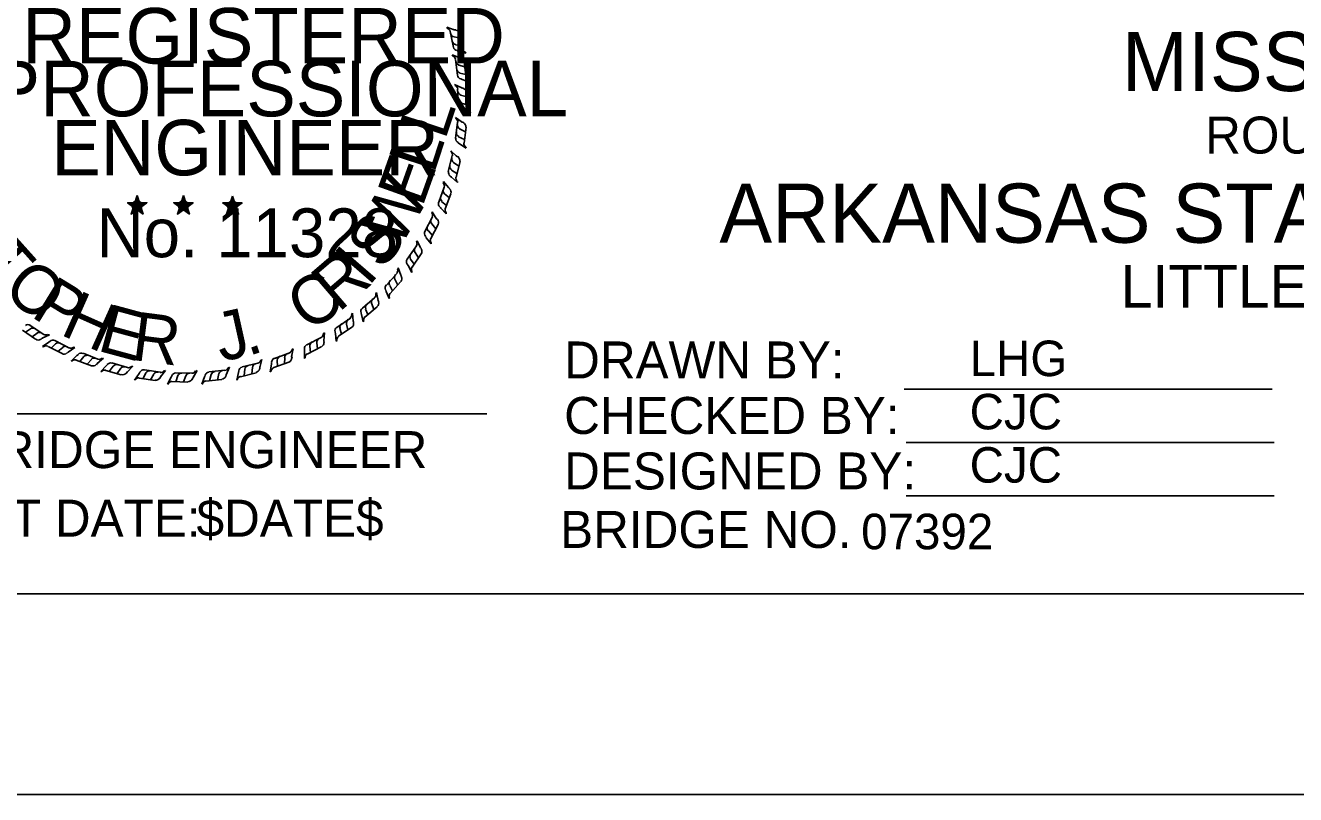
# Model space of a CAD drawing. Extents: x -193 to 149, y 507 to 725.
# Drawn here: x 58.22 to 101.13, y 507.07 to 533.07 of the extents above; entities that cross this region are included whole.
import ezdxf

# ---------------------------------------------------------------- set-up
doc = ezdxf.new("R2010")
doc.units = 0
for name, color, linetype in [('border', 7, 'Continuous'), ('Border 2660-Hwy18 - Level 62', 7, 'Continuous'), ('Border 2660-Hwy18 - Stamp-ChrisC', 7, 'Continuous'), ('Border 2660-Hwy18 - Text', 7, 'Continuous'), ('Border 2660-Hwy18 - Title Text', 7, 'Continuous'), ('Bridge No BLFR', 7, 'Continuous'), ('Text', 7, 'Continuous')]:
    doc.layers.add(name, color=color, linetype=linetype)

msp = doc.modelspace()

# ---------------------------------------------------------------- linework, layer by layer
at = {"layer": 'border'}
for p, q in [((87.907, 520.772), (100.339, 520.772)), ((52.387, 519.944), (73.807, 519.944)), ((87.979, 518.972), (100.411, 518.972)), ((87.979, 517.172), (100.411, 517.172)), ((143.779, 513.86), (-176.332, 513.86))]:
    msp.add_line(p, q, dxfattribs=at)
at = {"layer": 'Border 2660-Hwy18 - Level 62'}
msp.add_lwpolyline([(-192.533, 725.169), (148.651, 725.169), (148.651, 507.073), (-192.533, 507.073)], close=True, dxfattribs=at)
at = {"layer": 'Border 2660-Hwy18 - Stamp-ChrisC'}
for p, q in [((72.712, 532.92), (72.457, 533.01)), ((72.457, 533.01), (72.48, 532.965)), ((72.682, 532.328), (72.577, 532.868)), ((72.712, 532.92), (72.69, 532.928)), ((72.705, 532.68), (72.915, 532.643)), ((72.765, 532.92), (72.712, 532.92)), ((72.885, 532.785), (72.99, 532.26)), ((72.757, 532.41), (72.967, 532.388)), ((72.81, 532.215), (72.855, 532.2)), ((72.855, 532.2), (73.11, 532.133)), ((73.11, 532.133), (73.095, 532.155)), ((72.9, 531.975), (72.645, 532.073)), ((72.645, 532.073), (72.667, 532.035)), ((72.817, 531.383), (72.75, 531.923)), ((72.9, 531.975), (72.87, 531.975)), ((72.87, 531.728), (73.072, 531.675)), ((72.952, 531.968), (72.9, 531.975)), ((73.05, 531.825), (73.117, 531.285)), ((72.9, 531.458), (73.102, 531.413)), ((72.937, 531.263), (72.982, 531.24)), ((72.982, 531.24), (73.23, 531.15)), ((72.967, 530.955), (72.72, 531.075)), ((72.72, 531.075), (72.757, 531.038)), ((72.855, 530.37), (72.825, 530.918)), ((72.967, 530.955), (72.945, 530.963)), ((73.035, 530.94), (72.967, 530.955)), ((73.23, 531.15), (73.222, 531.18)), ((72.922, 530.708), (73.147, 530.655)), ((72.945, 530.445), (73.155, 530.385)), ((73.132, 530.798), (73.17, 530.258)), ((72.975, 529.8), (72.75, 529.958)), ((72.75, 529.958), (72.78, 529.913)), ((72.967, 530.243), (73.012, 530.22)), ((73.012, 530.22), (73.26, 530.115)), ((73.26, 530.115), (73.245, 530.145)), ((72.757, 529.253), (72.825, 529.8)), ((72.885, 529.575), (73.087, 529.47)), ((72.975, 529.8), (72.952, 529.815)), ((73.035, 529.785), (72.975, 529.8)), ((73.11, 529.628), (73.042, 529.095)), ((72.847, 529.103), (72.885, 529.073)), ((72.855, 529.305), (73.057, 529.215)), ((72.51, 528.128), (72.645, 528.668)), ((72.795, 528.645), (72.592, 528.833)), ((72.592, 528.833), (72.615, 528.788)), ((72.795, 528.645), (72.78, 528.668)), ((72.885, 529.073), (73.11, 528.923)), ((73.11, 528.923), (73.102, 528.96)), ((72.682, 528.435), (72.862, 528.308)), ((72.907, 528.465), (72.772, 527.94)), ((72.855, 528.623), (72.795, 528.645)), ((72.577, 527.978), (72.622, 527.94)), ((72.615, 528.173), (72.802, 528.06)), ((72.622, 527.94), (72.817, 527.76)), ((72.187, 527.093), (72.375, 527.603)), ((72.352, 527.79), (72.345, 527.745)), ((72.517, 527.588), (72.352, 527.79)), ((72.382, 527.378), (72.547, 527.243)), ((72.592, 527.378), (72.405, 526.875)), ((72.517, 527.588), (72.502, 527.595)), ((72.562, 527.55), (72.517, 527.588)), ((72.817, 527.76), (72.817, 527.798)), ((61.672, 527.078), (61.995, 526.973)), ((61.672, 527.078), (61.912, 527.055)), ((61.672, 527.078), (61.912, 527.033)), ((61.672, 527.078), (61.897, 527.018)), ((61.672, 527.078), (61.897, 526.988)), ((61.672, 527.078), (61.89, 526.965)), ((61.672, 527.078), (61.89, 526.943)), ((61.792, 526.695), (61.995, 526.973)), ((61.792, 526.695), (61.897, 526.958)), ((61.995, 527.318), (61.942, 527.085)), ((61.995, 527.318), (61.957, 527.078)), ((61.995, 527.318), (61.98, 527.078)), ((61.995, 526.973), (61.995, 527.318)), ((61.995, 527.318), (62.062, 527.078)), ((61.995, 527.318), (62.047, 527.078)), ((61.995, 527.318), (62.017, 527.085)), ((62.325, 527.078), (61.995, 526.973)), ((62.197, 526.695), (61.995, 526.973)), ((62.325, 527.078), (62.032, 527.055)), ((62.325, 527.078), (62.055, 527.033)), ((62.325, 527.078), (62.055, 527.01)), ((62.197, 526.695), (62.07, 526.965)), ((62.197, 526.695), (62.092, 526.973)), ((62.325, 527.078), (62.115, 526.995)), ((62.325, 527.078), (62.13, 526.98)), ((62.325, 527.078), (62.145, 526.973)), ((63.232, 527.078), (63.562, 526.973)), ((63.232, 527.078), (63.472, 527.055)), ((63.232, 527.078), (63.472, 527.033)), ((63.232, 527.078), (63.465, 527.018)), ((63.232, 527.078), (63.457, 526.988)), ((63.232, 527.078), (63.457, 526.965)), ((63.232, 527.078), (63.457, 526.943)), ((63.36, 526.695), (63.562, 526.973)), ((63.36, 526.695), (63.465, 526.958)), ((63.562, 527.318), (63.51, 527.085)), ((63.562, 527.318), (63.525, 527.078)), ((63.562, 527.318), (63.547, 527.078)), ((63.562, 526.973), (63.562, 527.318)), ((63.562, 527.318), (63.622, 527.078)), ((63.562, 527.318), (63.607, 527.078)), ((63.562, 527.318), (63.585, 527.085)), ((63.885, 527.078), (63.562, 526.973)), ((63.765, 526.695), (63.562, 526.973)), ((63.885, 527.078), (63.6, 527.055)), ((63.885, 527.078), (63.622, 527.033)), ((63.885, 527.078), (63.622, 527.01)), ((63.765, 526.695), (63.637, 526.965)), ((63.765, 526.695), (63.652, 526.973)), ((63.885, 527.078), (63.682, 526.995)), ((63.885, 527.078), (63.697, 526.98)), ((63.885, 527.078), (63.712, 526.973)), ((64.89, 527.07), (65.22, 526.965)), ((64.89, 527.07), (65.13, 527.04)), ((64.89, 527.07), (65.13, 527.025)), ((64.89, 527.07), (65.122, 527.01)), ((64.89, 527.07), (65.122, 526.973)), ((64.89, 527.07), (65.115, 526.95)), ((64.89, 527.07), (65.115, 526.935)), ((65.017, 526.688), (65.22, 526.965)), ((65.22, 527.303), (65.167, 527.078)), ((65.22, 527.303), (65.182, 527.07)), ((65.22, 527.303), (65.205, 527.07)), ((65.22, 526.965), (65.22, 527.303)), ((65.22, 527.303), (65.28, 527.07)), ((65.22, 527.303), (65.265, 527.07)), ((65.22, 527.303), (65.242, 527.07)), ((65.542, 527.07), (65.22, 526.965)), ((65.422, 526.688), (65.22, 526.965)), ((65.542, 527.07), (65.257, 527.048)), ((65.542, 527.07), (65.28, 527.018)), ((65.542, 527.07), (65.28, 527.003)), ((65.422, 526.688), (65.287, 526.958)), ((65.422, 526.688), (65.31, 526.958)), ((65.542, 527.07), (65.332, 526.98)), ((65.542, 527.07), (65.355, 526.973)), ((65.542, 527.07), (65.37, 526.958)), ((72.285, 527.123), (72.45, 526.988)), ((61.792, 526.695), (61.912, 526.928)), ((61.792, 526.695), (61.927, 526.913)), ((61.792, 526.695), (61.995, 526.898)), ((61.792, 526.695), (61.957, 526.89)), ((61.792, 526.695), (62.002, 526.875)), ((62.197, 526.695), (61.995, 526.898)), ((62.197, 526.695), (61.995, 526.868)), ((62.197, 526.695), (62.032, 526.89)), ((62.197, 526.695), (62.062, 526.928)), ((63.36, 526.695), (63.48, 526.928)), ((63.36, 526.695), (63.495, 526.913)), ((63.36, 526.695), (63.562, 526.898)), ((63.36, 526.695), (63.525, 526.89)), ((63.36, 526.695), (63.57, 526.875)), ((63.765, 526.695), (63.562, 526.898)), ((63.765, 526.695), (63.562, 526.868)), ((63.765, 526.695), (63.592, 526.89)), ((63.765, 526.695), (63.622, 526.928)), ((65.017, 526.688), (65.122, 526.943)), ((65.017, 526.688), (65.137, 526.913)), ((65.017, 526.688), (65.152, 526.905)), ((65.017, 526.688), (65.182, 526.883)), ((65.017, 526.688), (65.212, 526.883)), ((65.017, 526.688), (65.227, 526.86)), ((65.422, 526.688), (65.212, 526.883)), ((65.422, 526.688), (65.212, 526.86)), ((65.422, 526.688), (65.257, 526.883)), ((65.422, 526.688), (65.287, 526.913)), ((71.722, 526.103), (71.977, 526.598)), ((71.962, 526.77), (71.955, 526.725)), ((72.105, 526.545), (71.962, 526.77)), ((72.105, 526.545), (72.097, 526.568)), ((72.15, 526.508), (72.105, 526.545)), ((72.232, 526.928), (72.262, 526.89)), ((72.262, 526.89), (72.442, 526.703)), ((72.442, 526.703), (72.442, 526.733)), ((71.835, 526.125), (71.97, 525.975)), ((72.165, 526.343), (71.917, 525.863)), ((71.955, 526.365), (72.09, 526.2)), ((71.452, 525.788), (71.437, 525.743)), ((71.565, 525.555), (71.452, 525.788)), ((71.745, 525.938), (71.767, 525.893)), ((71.767, 525.893), (71.925, 525.683)), ((71.925, 525.683), (71.932, 525.72)), ((71.122, 525.165), (71.437, 525.615)), ((71.595, 525.345), (71.287, 524.903)), ((71.392, 525.39), (71.505, 525.21)), ((71.565, 525.555), (71.55, 525.578)), ((71.602, 525.518), (71.565, 525.555)), ((70.815, 524.88), (70.8, 524.835)), ((70.905, 524.625), (70.815, 524.88)), ((71.122, 525), (71.152, 524.955)), ((71.152, 524.955), (71.272, 524.715)), ((71.235, 525.165), (71.355, 525)), ((70.417, 524.288), (70.777, 524.7)), ((70.897, 524.408), (70.545, 524.01)), ((70.702, 524.49), (70.8, 524.295)), ((70.905, 524.625), (70.89, 524.648)), ((70.927, 524.58), (70.905, 524.625)), ((71.272, 524.715), (71.28, 524.753)), ((70.087, 524.04), (70.065, 524.003)), ((70.14, 523.778), (70.087, 524.04)), ((70.395, 524.123), (70.41, 524.078)), ((70.41, 524.078), (70.507, 523.838)), ((70.53, 524.28), (70.627, 524.1)), ((69.607, 523.515), (70.02, 523.868)), ((70.102, 523.56), (69.69, 523.215)), ((69.922, 523.665), (69.99, 523.463)), ((70.14, 523.778), (70.132, 523.8)), ((70.162, 523.725), (70.14, 523.778)), ((70.507, 523.838), (70.522, 523.86)), ((68.745, 522.863), (69.202, 523.178)), ((69.277, 523.343), (69.24, 523.305)), ((69.3, 523.073), (69.277, 523.343)), ((69.3, 523.073), (69.3, 523.103)), ((69.562, 523.35), (69.577, 523.305)), ((69.577, 523.305), (69.637, 523.05)), ((69.712, 523.485), (69.787, 523.298)), ((58.567, 522.465), (58.125, 522.765)), ((58.395, 522.81), (58.23, 522.698)), ((58.387, 522.923), (58.845, 522.623)), ((58.62, 522.668), (58.455, 522.548)), ((68.325, 522.675), (68.287, 522.645)), ((68.31, 522.413), (68.325, 522.675)), ((68.692, 522.705), (68.7, 522.653)), ((69.255, 522.87), (68.805, 522.563)), ((68.85, 522.833), (68.902, 522.63)), ((69.075, 522.975), (69.112, 522.78)), ((69.315, 523.028), (69.3, 523.073)), ((69.637, 523.05), (69.652, 523.073)), ((58.747, 522.458), (58.785, 522.495)), ((58.785, 522.495), (59.032, 522.608)), ((58.785, 522.495), (58.807, 522.503)), ((59.017, 522.368), (58.8, 522.218)), ((59.032, 522.608), (58.987, 522.615)), ((59.055, 522.398), (59.017, 522.368)), ((59.242, 522.308), (59.092, 522.165)), ((59.22, 522.42), (59.715, 522.165)), ((67.732, 522.278), (68.212, 522.525)), ((68.07, 522.345), (68.092, 522.135)), ((68.31, 522.413), (68.302, 522.435)), ((68.317, 522.353), (68.31, 522.413)), ((68.7, 522.653), (68.722, 522.398)), ((68.722, 522.398), (68.752, 522.42)), ((58.8, 522.218), (58.837, 522.203)), ((59.467, 521.978), (58.987, 522.218)), ((59.482, 522.188), (59.317, 522.053)), ((59.632, 521.993), (59.662, 522.03)), ((59.662, 522.03), (59.895, 522.18)), ((59.662, 522.03), (59.692, 522.045)), ((59.962, 521.91), (59.767, 521.723)), ((59.895, 522.18), (59.842, 522.188)), ((60, 521.94), (59.962, 521.91)), ((60.195, 521.88), (60.06, 521.715)), ((60.172, 521.993), (60.675, 521.79)), ((60.652, 521.64), (60.862, 521.82)), ((60.862, 521.82), (60.81, 521.805)), ((66.637, 521.813), (67.155, 522.008)), ((66.982, 521.843), (66.975, 521.633)), ((67.215, 521.88), (67.267, 522.143)), ((67.215, 521.88), (67.222, 521.91)), ((67.23, 521.828), (67.215, 521.88)), ((67.267, 522.143), (67.23, 522.113)), ((67.65, 522.128), (67.65, 522.075)), ((67.65, 522.075), (67.65, 521.813)), ((67.65, 521.813), (67.672, 521.835)), ((68.22, 522.21), (67.747, 521.963)), ((67.83, 522.225), (67.852, 522.015)), ((59.767, 521.723), (59.805, 521.73)), ((60.45, 521.565), (59.94, 521.76)), ((60.45, 521.783), (60.307, 521.618)), ((60.622, 521.595), (60.652, 521.64)), ((60.652, 521.64), (60.667, 521.655)), ((60.952, 521.565), (60.772, 521.37)), ((60.772, 521.37), (60.802, 521.378)), ((61.462, 521.265), (60.937, 521.408)), ((60.99, 521.603), (60.952, 521.565)), ((61.185, 521.558), (61.057, 521.37)), ((61.147, 521.663), (61.672, 521.505)), ((61.447, 521.483), (61.32, 521.303)), ((61.657, 521.355), (61.852, 521.55)), ((61.657, 521.355), (61.672, 521.37)), ((61.852, 521.55), (61.8, 521.535)), ((62.242, 521.43), (62.782, 521.348)), ((62.79, 521.198), (62.955, 521.408)), ((62.955, 521.408), (62.91, 521.385)), ((63.885, 521.168), (64.02, 521.408)), ((64.02, 521.408), (63.975, 521.378)), ((64.425, 521.363), (64.965, 521.415)), ((65.01, 521.265), (65.122, 521.52)), ((65.122, 521.52), (65.077, 521.483)), ((65.437, 521.393), (65.422, 521.34)), ((65.542, 521.528), (66.075, 521.655)), ((65.632, 521.453), (65.617, 521.235)), ((65.895, 521.513), (65.872, 521.295)), ((66.142, 521.513), (66.21, 521.783)), ((66.142, 521.513), (66.142, 521.543)), ((66.142, 521.453), (66.142, 521.513)), ((66.21, 521.783), (66.18, 521.738)), ((66.54, 521.625), (66.495, 521.363)), ((66.495, 521.363), (66.525, 521.385)), ((66.54, 521.678), (66.54, 521.625)), ((67.125, 521.693), (66.615, 521.505)), ((66.727, 521.753), (66.735, 521.543)), ((61.627, 521.303), (61.657, 521.355)), ((62.062, 521.31), (61.905, 521.085)), ((61.905, 521.085), (61.935, 521.1)), ((62.092, 521.348), (62.062, 521.31)), ((62.602, 521.07), (62.07, 521.153)), ((62.295, 521.333), (62.197, 521.138)), ((62.557, 521.288), (62.452, 521.093)), ((62.76, 521.138), (62.79, 521.198)), ((62.79, 521.198), (62.797, 521.213)), ((63.15, 521.183), (63.022, 520.943)), ((63.022, 520.943), (63.052, 520.958)), ((63.172, 521.228), (63.15, 521.183)), ((63.712, 521.018), (63.172, 521.033)), ((63.3, 521.325), (63.847, 521.318)), ((63.375, 521.235), (63.3, 521.025)), ((63.645, 521.228), (63.562, 521.025)), ((63.862, 521.108), (63.885, 521.168)), ((63.885, 521.168), (63.892, 521.19)), ((64.275, 521.198), (64.185, 520.943)), ((64.185, 520.943), (64.215, 520.965)), ((64.297, 521.243), (64.275, 521.198)), ((64.86, 521.1), (64.32, 521.048)), ((64.5, 521.273), (64.447, 521.063)), ((64.762, 521.303), (64.71, 521.085)), ((64.995, 521.205), (65.01, 521.265)), ((65.01, 521.265), (65.017, 521.288)), ((65.422, 521.34), (65.362, 521.078)), ((65.362, 521.078), (65.392, 521.108)), ((66.015, 521.333), (65.49, 521.198))]:
    msp.add_line(p, q, dxfattribs=at)
for points in [[(61.995, 527.318), (62.197, 526.695), (61.672, 527.078), (62.325, 527.078), (61.792, 526.695), (61.995, 527.318)], [(63.562, 527.318), (63.765, 526.695), (63.232, 527.078), (63.885, 527.078), (63.36, 526.695), (63.562, 527.318)], [(65.22, 527.303), (65.422, 526.688), (64.89, 527.07), (65.542, 527.07), (65.017, 526.688), (65.22, 527.303)]]:
    msp.add_lwpolyline(points, dxfattribs=at)
for centre, radius in [((61.994, 526.977), 0.161), ((61.994, 526.977), 0.146), ((61.994, 526.977), 0.136), ((61.994, 526.977), 0.124), ((61.994, 526.977), 0.109), ((61.994, 526.977), 0.101), ((61.994, 526.977), 0.0929), ((61.994, 526.977), 0.08), ((61.994, 526.977), 0.0701), ((61.994, 526.977), 0.0583), ((61.994, 526.977), 0.0464), ((61.994, 526.977), 0.0346), ((61.994, 526.977), 0.0278), ((61.994, 526.977), 0.0135), ((63.559, 526.977), 0.161), ((63.559, 526.977), 0.146), ((63.559, 526.977), 0.136), ((63.559, 526.977), 0.124), ((63.559, 526.977), 0.109), ((63.559, 526.977), 0.101), ((63.559, 526.977), 0.0929), ((63.559, 526.977), 0.08), ((63.559, 526.977), 0.0701), ((63.559, 526.977), 0.0583), ((63.559, 526.977), 0.0464), ((63.559, 526.977), 0.0346), ((63.559, 526.977), 0.0278), ((63.559, 526.977), 0.0135), ((65.216, 526.966), 0.161), ((65.216, 526.966), 0.146), ((65.216, 526.966), 0.136), ((65.216, 526.966), 0.124), ((65.216, 526.966), 0.109), ((65.216, 526.966), 0.101), ((65.216, 526.966), 0.0929), ((65.216, 526.966), 0.08), ((65.216, 526.966), 0.0701), ((65.216, 526.966), 0.0583), ((65.216, 526.966), 0.0464), ((65.216, 526.966), 0.0346), ((65.216, 526.966), 0.0278), ((65.216, 526.966), 0.0135)]:
    msp.add_circle(centre, radius, dxfattribs=at)
for centre, start, end in [((72.435, 532.829), 15.7912, 74.579), ((72.735, 532.826), 191.5304, 259.9044), ((72.787, 532.566), 191.5304, 259.9044), ((72.738, 532.768), 11.5304, 79.9044), ((72.828, 532.365), 191.5304, 259.9044), ((73.131, 532.305), 195.7912, 254.579), ((72.609, 531.898), 11.4348, 70.2227), ((72.908, 531.872), 187.174, 255.548), ((72.907, 531.814), 7.174, 75.548), ((72.94, 531.609), 187.174, 255.548), ((72.967, 531.406), 187.174, 255.548), ((73.264, 531.322), 191.4348, 250.2227), ((72.684, 530.9), 8.033, 66.8208), ((72.981, 530.857), 183.7722, 252.1462), ((72.976, 530.799), 3.7722, 72.1462), ((72.997, 530.593), 183.7722, 252.1462), ((73.011, 530.388), 183.7722, 252.1462), ((73.303, 530.287), 188.033, 246.8208), ((72.682, 529.802), 357.57, 56.3579), ((72.966, 529.705), 173.3093, 241.6832), ((72.951, 529.649), 353.3093, 61.6832), ((72.911, 529.238), 173.3093, 241.6832), ((72.934, 529.442), 173.3093, 241.6832), ((72.504, 528.687), 350.445, 49.2329), ((73.18, 529.086), 177.57, 236.3579), ((72.71, 528.3), 166.1842, 234.5582), ((72.774, 528.556), 166.1842, 234.5582), ((72.752, 528.503), 346.1842, 54.5582), ((72.662, 528.1), 166.1842, 234.5582), ((72.91, 527.916), 170.445, 229.2329), ((72.484, 527.487), 159.9003, 228.2743), ((72.23, 527.647), 344.1611, 42.9489), ((72.457, 527.436), 339.9003, 48.2743), ((72.322, 527.046), 159.9003, 228.2743), ((72.392, 527.239), 159.9003, 228.2743), ((72.065, 526.46), 152.8541, 221.2281), ((71.833, 526.65), 337.1149, 35.9028), ((72.549, 526.836), 164.1611, 222.9489), ((71.85, 526.042), 152.8541, 221.2281), ((71.944, 526.225), 152.8541, 221.2281), ((72.031, 526.413), 332.8541, 41.2281), ((71.304, 525.691), 329.7262, 28.514), ((72.049, 525.806), 157.1149, 215.9028), ((71.359, 525.255), 145.4654, 213.8394), ((71.51, 525.472), 145.4654, 213.8394), ((71.471, 525.43), 325.4654, 33.8394), ((70.656, 524.793), 322.7822, 21.57), ((71.244, 525.086), 145.4654, 213.8394), ((71.41, 524.825), 149.7262, 208.514), ((70.659, 524.354), 138.5214, 206.8953), ((70.834, 524.551), 138.5214, 206.8953), ((70.79, 524.514), 318.5214, 26.8953), ((69.917, 523.974), 314.7826, 13.5704), ((70.523, 524.2), 138.5214, 206.8953), ((70.657, 523.921), 142.7822, 201.57), ((69.702, 523.406), 130.5218, 198.8958), ((69.858, 523.54), 130.5218, 198.8958), ((70.06, 523.711), 130.5218, 198.8958), ((70.011, 523.68), 310.5218, 18.8958), ((69.216, 523.015), 124.6526, 193.0266), ((69.101, 523.293), 308.9134, 7.7012), ((69.796, 523.111), 134.7826, 193.5704), ((58.308, 522.808), 56.1736, 124.5476), ((58.478, 522.694), 56.1736, 124.5476), ((58.698, 522.546), 56.1736, 124.5476), ((68.829, 522.749), 124.6526, 193.0266), ((68.998, 522.866), 124.6526, 193.0266), ((69.164, 522.99), 304.6526, 13.0266), ((58.655, 522.585), 236.1736, 304.5476), ((58.92, 522.09), 67.3316, 126.1194), ((58.913, 522.755), 240.4344, 299.2222), ((59.156, 522.29), 63.0708, 131.4448), ((59.339, 522.197), 63.0708, 131.4448), ((67.795, 522.148), 116.8386, 185.2126), ((67.978, 522.242), 116.8386, 185.2126), ((68.215, 522.36), 116.8386, 185.2126), ((68.138, 522.65), 301.0994, 359.8872), ((68.16, 522.342), 296.8386, 5.2126), ((68.892, 522.446), 128.9134, 187.7013), ((59.528, 522.11), 243.0708, 311.4448), ((59.575, 522.077), 63.0708, 131.4448), ((59.764, 522.31), 247.3316, 306.1194), ((60.113, 521.848), 69.0955, 137.4695), ((60.305, 521.775), 69.0955, 137.4695), ((60.552, 521.68), 69.0955, 137.4695), ((60.715, 521.932), 253.3563, 312.1441), ((66.687, 521.68), 110.4724, 178.8463), ((66.879, 521.752), 110.4724, 178.8463), ((67.127, 521.844), 110.4724, 178.8463), ((67.071, 521.832), 290.4724, 358.8463), ((67.083, 522.141), 294.7331, 353.521), ((67.817, 521.84), 121.0994, 179.8872), ((59.9, 521.625), 73.3563, 132.1441), ((60.502, 521.708), 249.0955, 317.4695), ((60.911, 521.275), 78.2517, 137.0395), ((61.105, 521.515), 73.9909, 142.3649), ((61.302, 521.459), 73.9909, 142.3649), ((61.556, 521.385), 73.9909, 142.3649), ((61.697, 521.65), 258.2517, 317.0395), ((62.217, 521.28), 81.4231, 149.797), ((62.42, 521.25), 81.4231, 149.797), ((62.787, 521.49), 265.6839, 324.4717), ((63.841, 521.46), 273.4236, 332.2115), ((64.642, 521.229), 95.6641, 164.0381), ((64.905, 521.254), 95.6641, 164.0381), ((64.939, 521.552), 279.9249, 338.7128), ((65.582, 521.379), 103.9066, 172.2806), ((65.781, 521.429), 103.9066, 172.2806), ((66.038, 521.491), 103.9066, 172.2806), ((65.981, 521.486), 283.9066, 352.2806), ((66.029, 521.791), 288.1674, 346.9552), ((66.674, 521.371), 114.7331, 173.521), ((61.503, 521.409), 253.9909, 322.3649), ((62.056, 521.016), 85.6839, 144.4717), ((62.681, 521.209), 81.4231, 149.797), ((62.626, 521.226), 261.4231, 329.797), ((63.18, 520.892), 93.4236, 152.2115), ((63.304, 521.175), 89.1628, 157.5368), ((63.509, 521.173), 89.1628, 157.5368), ((63.774, 521.168), 89.1628, 157.5368), ((63.717, 521.177), 269.1628, 337.5368), ((64.346, 520.912), 99.9249, 158.7128), ((64.437, 521.208), 95.6641, 164.0381), ((64.847, 521.257), 275.6641, 344.0381), ((65.534, 521.073), 108.1674, 166.9552)]:
    msp.add_arc(centre, 0.148, start, end, dxfattribs=at)

# ---------------------------------------------------------------- texts
for s, height, p in [('REGISTERED', 1.875, (58.12, 531.783)), ('PROFESSIONAL', 1.87497, (57.047, 529.998)), ('ENGINEER', 1.875, (59.095, 528.003)), ('No. 11328', 1.65, (60.626, 525.236))]:
    msp.add_text(s, height=height, dxfattribs=at).set_placement(p)
for s, rotation, p in [('L', 71.6828, (72.398, 529.166)), ('L', 71.6828, (72.021, 528.027)), ('E', 70.3031, (71.627, 526.895)), ('W', 60.0948, (70.868, 525.514)), ('S', 53.9956, (70.301, 524.761)), ('T', 311.8122, (56.519, 525.026)), ('R', 40.6231, (68.8, 523.346)), ('I', 49.2381, (69.805, 524.217)), ('O', 320.3433, (57.401, 524.048)), ('P', 328.4551, (58.367, 523.249)), ('C', 32.5951, (67.755, 522.678)), ('H', 335.98, (59.355, 522.637)), ('E', 344.8465, (60.61, 522.089)), ('R', 352.6229, (61.769, 521.772)), ('J', 12.5364, (64.831, 521.696)), ('.', 18.5518, (65.741, 521.882))]:
    msp.add_text(s, height=1.642, rotation=rotation, dxfattribs=at).set_placement(p)
at = {"layer": 'Border 2660-Hwy18 - Text'}
for s, p in [('DRAWN BY:', (76.423, 521.137)), ('CHECKED BY:', (76.423, 519.262)), ('BRIDGE ENGINEER', (56.199, 518.108)), ('DESIGNED BY:', (76.423, 517.387)), ('PRINT DATE:', (53.739, 515.791)), ('BRIDGE NO.', (76.288, 515.41))]:
    msp.add_text(s, height=1.25, dxfattribs=at).set_placement(p)
msp.add_text('$DATE$', height=1.25, rotation=359.9999, dxfattribs=at).set_placement((64.005, 515.791))
at = {"layer": 'Border 2660-Hwy18 - Title Text'}
for s, height, p in [('MISSISSIPPI  COUNTY', 1.99999, (95.269, 530.85)), ('ROUTE 18      SEC. 6', 1.25, (98.078, 528.739)), ('ARKANSAS STATE HIGHWAY COMMISSION', 1.99999, (81.666, 525.724)), ('LITTLE ROCK, ARKANSAS', 1.44, (95.227, 523.532))]:
    msp.add_text(s, height=height, dxfattribs=at).set_placement(p)
at = {"layer": 'Bridge No BLFR'}
msp.add_text('07392', height=1.2, dxfattribs=at).set_placement((86.457, 515.366))
at = {"layer": 'Text'}
for s, p in [('LHG', (90.122, 521.217)), ('CJC', (90.122, 519.417)), ('CJC', (90.122, 517.617))]:
    msp.add_text(s, height=1.2, dxfattribs=at).set_placement(p)

doc.saveas('drawing.dxf')
